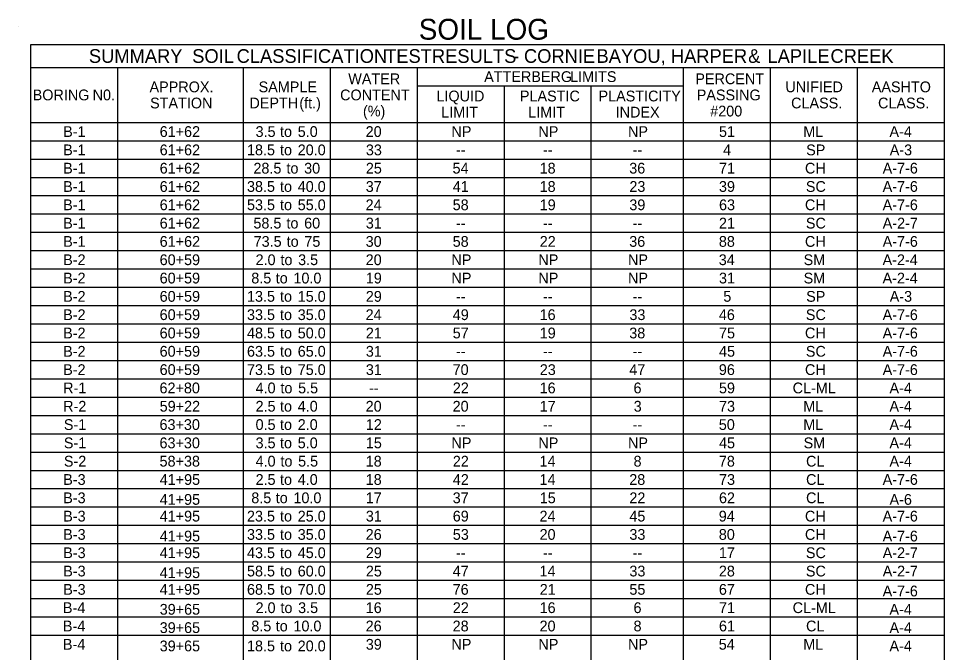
# Model space of a CAD drawing. Extents: x 977434 to 989596, y 1525697 to 1528336.
# Drawn here: x 977434 to 977967, y 1527885 to 1528249 of the extents above; entities that cross this region are included whole.
import ezdxf

# ---------------------------------------------------------------- set-up
doc = ezdxf.new("R2010")
doc.units = 0
doc.layers.add('Default', color=7, linetype='Continuous')
doc.layers.add('R_Border Prem', color=7, linetype='Continuous')

msp = doc.modelspace()

# ---------------------------------------------------------------- linework, layer by layer
at = {"layer": 'Default'}
for p, q in [((977441.26, 1528234.33), (977966.88, 1528234.33)), ((977441.26, 1528234.33), (977966.88, 1528234.33)), ((977441.26, 1527568.31), (977441.26, 1528234.33)), ((977441.26, 1527568.31), (977441.26, 1528234.33)), ((977966.88, 1527568.31), (977966.88, 1528234.33)), ((977966.88, 1527568.31), (977966.88, 1528234.33)), ((977441.26, 1528221.17), (977966.88, 1528221.17)), ((977491.28, 1527568.31), (977491.28, 1528221.17)), ((977563.67, 1527568.31), (977563.67, 1528221.17)), ((977613.69, 1527568.31), (977613.69, 1528221.17)), ((977663.71, 1527568.31), (977663.71, 1528221.17)), ((977816.83, 1527568.31), (977816.83, 1528221.17)), ((977866.85, 1527568.31), (977866.85, 1528221.17)), ((977916.87, 1527568.31), (977916.87, 1528221.17)), ((977663.71, 1528210.64), (977816.83, 1528210.64)), ((977713.72, 1527568.31), (977713.72, 1528210.64)), ((977763.74, 1527568.31), (977763.74, 1528210.64)), ((977441.26, 1528189.58), (977966.88, 1528189.58)), ((977816.83, 1528189.58), (977966.88, 1528189.58)), ((977441.26, 1528179.05), (977966.88, 1528179.05)), ((977441.26, 1528168.52), (977966.88, 1528168.52)), ((977441.26, 1528157.99), (977966.88, 1528157.99)), ((977441.26, 1528147.46), (977966.88, 1528147.46)), ((977441.26, 1528136.93), (977966.88, 1528136.93)), ((977441.26, 1528126.4), (977966.88, 1528126.4)), ((977441.26, 1528115.87), (977966.88, 1528115.87)), ((977441.26, 1528105.34), (977966.88, 1528105.34)), ((977441.26, 1528094.81), (977966.88, 1528094.81)), ((977441.26, 1528084.28), (977966.88, 1528084.28)), ((977441.26, 1528073.75), (977966.88, 1528073.75)), ((977441.26, 1528063.22), (977966.88, 1528063.22)), ((977441.26, 1528052.69), (977966.88, 1528052.69)), ((977441.26, 1528042.16), (977966.88, 1528042.16)), ((977441.26, 1528031.63), (977966.88, 1528031.63)), ((977441.26, 1528021.1), (977966.88, 1528021.1)), ((977441.26, 1528010.57), (977966.88, 1528010.57)), ((977441.26, 1528000.04), (977966.88, 1528000.04)), ((977441.26, 1527989.51), (977966.88, 1527989.51)), ((977441.26, 1527978.98), (977966.88, 1527978.98)), ((977441.26, 1527968.45), (977966.88, 1527968.45)), ((977441.26, 1527957.92), (977966.88, 1527957.92)), ((977441.26, 1527947.39), (977966.88, 1527947.39)), ((977441.26, 1527936.86), (977966.88, 1527936.86)), ((977441.26, 1527926.33), (977966.88, 1527926.33)), ((977441.26, 1527915.8), (977966.88, 1527915.8)), ((977441.26, 1527905.27), (977966.88, 1527905.27)), ((977441.26, 1527894.74), (977966.88, 1527894.74))]:
    msp.add_line(p, q, dxfattribs=at)
at = {"layer": 'R_Border Prem'}
msp.add_line((977434.24, 1528244.86), (977434.24, 1528244.86), dxfattribs=at)

# ---------------------------------------------------------------- texts
at = {"layer": 'Default'}
for s, height, p in [('SOIL LOG ', 12, (977664.46, 1528237.13)), ('SUMMARY', 7.875, (977474.72, 1528223.81)), (' SOIL', 7.875, (977531.24, 1528223.81)), (' CLASSIFICATION', 7.875, (977556.77, 1528223.81)), (' TEST', 7.875, (977642.19, 1528223.81)), (' RESULTS', 7.875, (977669.12, 1528223.81)), (' CORNIE', 7.875, (977722.06, 1528223.81)), (' BAYOU,', 7.875, (977763.79, 1528223.81)), (' HARPER', 7.875, (977806.56, 1528223.81)), (' &', 7.875, (977851.04, 1528223.81)), (' LAPILE', 7.875, (977862.14, 1528223.81)), (' CREEK', 7.875, (977898.37, 1528223.81)), (' -', 7.875, (977715.82, 1528223.81)), ('WATER', 6.188, (977623.91, 1528211.56)), ('ATTERBERG', 6.188, (977702.1, 1528212.81)), (' LIMITS', 6.188, (977749.24, 1528212.81)), ('PERCENT', 6.188, (977823.57, 1528211.56)), ('APPROX.', 6.188, (977509.6, 1528206.92)), ('SAMPLE', 6.188, (977572.34, 1528206.92)), ('UNIFIED', 6.188, (977875.36, 1528206.92)), ('AASHTO', 6.188, (977925.06, 1528206.92)), ('BORING', 6.188, (977442.39, 1528202.28)), (' N0.', 6.188, (977474.57, 1528202.28)), ('CONTENT', 6.188, (977619.23, 1528202.28)), ('LIQUID', 6.188, (977674.63, 1528201.66)), ('PLASTIC', 6.188, (977722.64, 1528201.66)), ('PLASTICITY', 6.188, (977767.87, 1528201.66)), ('PASSING', 6.188, (977824.37, 1528202.28)), ('STATION', 6.188, (977509.92, 1528197.64)), ('DEPTH', 6.188, (977567.06, 1528197.64)), (' (ft.)', 6.188, (977593.46, 1528197.64)), ('(%)', 6.188, (977632.36, 1528193)), ('#200', 6.188, (977832.13, 1528193)), ('CLASS.', 6.188, (977878.65, 1528197.64)), ('CLASS.', 6.188, (977928.67, 1528197.64)), ('LIMIT', 6.188, (977677.41, 1528192.38)), ('LIMIT', 6.188, (977727.43, 1528192.38)), ('INDEX', 6.188, (977777.73, 1528192.38)), ('B-1', 6.188, (977459.92, 1528181.22)), ('61+62', 6.188, (977515.44, 1528181.22)), ('3.5', 6.188, (977570.6, 1528181.22)), (' to', 6.188, (977582.37, 1528181.22)), (' 5.0', 6.188, (977592.55, 1528181.22)), ('20', 6.188, (977633.93, 1528181.22)), ('NP', 6.188, (977683.27, 1528181.22)), ('NP', 6.188, (977733.29, 1528181.22)), ('NP', 6.188, (977784.84, 1528181.22)), ('51', 6.188, (977837.16, 1528181.22)), ('ML', 6.188, (977885.68, 1528181.22)), ('A-4', 6.188, (977935.23, 1528181.22)), ('B-1', 6.188, (977459.92, 1528170.69)), ('61+62', 6.188, (977515.44, 1528170.69)), ('18.5', 6.188, (977565.66, 1528170.69)), (' to', 6.188, (977582.37, 1528170.69)), (' 20.0', 6.188, (977592.55, 1528170.69)), ('33', 6.188, (977634.06, 1528170.69)), ('--', 6.188, (977685.89, 1528170.69)), ('--', 6.188, (977735.91, 1528170.69)), ('--', 6.188, (977787.46, 1528170.69)), ('4', 6.19, (977839.51, 1528170.69)), ('SP', 6.188, (977887.32, 1528170.69)), ('A-3', 6.188, (977935.39, 1528170.69)), ('B-1', 6.188, (977459.92, 1528160.16)), ('61+62', 6.188, (977515.44, 1528160.16)), ('28.5', 6.188, (977569.37, 1528160.16)), (' to', 6.188, (977586.07, 1528160.16)), (' 30', 6.188, (977596.25, 1528160.16)), ('25', 6.188, (977634.04, 1528160.16)), ('54', 6.188, (977683.92, 1528160.16)), ('18', 6.188, (977733.99, 1528160.16)), ('36', 6.188, (977785.54, 1528160.16)), ('71', 6.188, (977837.16, 1528160.16)), ('CH', 6.188, (977886.63, 1528160.16)), ('A-7-6', 6.188, (977931.32, 1528160.16)), ('B-1', 6.188, (977459.92, 1528149.63)), ('61+62', 6.188, (977515.44, 1528149.63)), ('38.5', 6.188, (977565.66, 1528149.63)), (' to', 6.188, (977582.37, 1528149.63)), (' 40.0', 6.188, (977592.55, 1528149.63)), ('37', 6.188, (977633.98, 1528149.63)), ('41', 6.188, (977684.04, 1528149.63)), ('18', 6.188, (977733.99, 1528149.63)), ('23', 6.188, (977785.64, 1528149.63)), ('39', 6.188, (977837.15, 1528149.63)), ('SC', 6.188, (977887.15, 1528149.63)), ('A-7-6', 6.188, (977931.32, 1528149.63)), ('B-1', 6.188, (977459.92, 1528139.1)), ('61+62', 6.188, (977515.44, 1528139.1)), ('53.5', 6.188, (977565.66, 1528139.1)), (' to', 6.188, (977582.37, 1528139.1)), (' 55.0', 6.188, (977592.55, 1528139.1)), ('24', 6.188, (977633.9, 1528139.1)), ('58', 6.188, (977683.98, 1528139.1)), ('19', 6.188, (977734.04, 1528139.1)), ('39', 6.188, (977785.59, 1528139.1)), ('63', 6.188, (977837.2, 1528139.1)), ('CH', 6.188, (977886.63, 1528139.1)), ('A-7-6', 6.188, (977931.32, 1528139.1)), ('B-1', 6.188, (977459.92, 1528128.57)), ('61+62', 6.188, (977515.44, 1528128.57)), ('58.5', 6.188, (977569.37, 1528128.57)), (' to', 6.188, (977586.07, 1528128.57)), (' 60', 6.188, (977596.25, 1528128.57)), ('31', 6.188, (977634.02, 1528128.57)), ('--', 6.188, (977685.89, 1528128.57)), ('--', 6.188, (977735.91, 1528128.57)), ('--', 6.188, (977787.46, 1528128.57)), ('21', 6.188, (977837.16, 1528128.57)), ('SC', 6.188, (977887.15, 1528128.57)), ('A-2-7', 6.188, (977931.35, 1528128.57)), ('B-1', 6.188, (977459.92, 1528118.04)), ('61+62', 6.188, (977515.44, 1528118.04)), ('73.5', 6.188, (977569.48, 1528118.04)), (' to', 6.188, (977586.19, 1528118.04)), (' 75', 6.188, (977596.37, 1528118.04)), ('30', 6.188, (977633.93, 1528118.04)), ('58', 6.188, (977683.98, 1528118.04)), ('22', 6.188, (977734.06, 1528118.04)), ('36', 6.188, (977785.54, 1528118.04)), ('88', 6.188, (977837.1, 1528118.04)), ('CH', 6.188, (977886.63, 1528118.04)), ('A-7-6', 6.188, (977931.32, 1528118.04)), ('B-2', 6.188, (977459.92, 1528107.51)), ('60+59', 6.188, (977515.42, 1528107.51)), ('2.0', 6.188, (977570.6, 1528107.51)), (' to', 6.188, (977582.61, 1528107.51)), (' 3.5', 6.188, (977592.78, 1528107.51)), ('20', 6.188, (977633.93, 1528107.51)), ('NP', 6.188, (977683.27, 1528107.51)), ('NP', 6.188, (977733.29, 1528107.51)), ('NP', 6.188, (977784.84, 1528107.51)), ('34', 6.188, (977837.04, 1528107.51)), ('SM', 6.188, (977885.86, 1528107.51)), ('A-2-4', 6.188, (977931.27, 1528107.51)), ('B-2', 6.188, (977459.92, 1528096.98)), ('60+59', 6.188, (977515.42, 1528096.98)), ('8.5', 6.188, (977568.13, 1528096.98)), (' to', 6.188, (977579.9, 1528096.98)), (' 10.0', 6.188, (977590.08, 1528096.98)), ('19', 6.188, (977634.01, 1528096.98)), ('NP', 6.188, (977683.27, 1528096.98)), ('NP', 6.188, (977733.29, 1528096.98)), ('NP', 6.188, (977784.84, 1528096.98)), ('31', 6.188, (977837.16, 1528096.98)), ('SM', 6.188, (977885.86, 1528096.98)), ('A-2-4', 6.188, (977931.27, 1528096.98)), ('B-2', 6.188, (977459.92, 1528086.45)), ('60+59', 6.188, (977515.42, 1528086.45)), ('13.5', 6.188, (977565.66, 1528086.45)), (' to', 6.188, (977582.37, 1528086.45)), (' 15.0', 6.188, (977592.55, 1528086.45)), ('29', 6.188, (977634.01, 1528086.45)), ('--', 6.188, (977685.89, 1528086.45)), ('--', 6.188, (977735.91, 1528086.45)), ('--', 6.188, (977787.46, 1528086.45)), ('5', 6.19, (977839.65, 1528086.45)), ('SP', 6.188, (977887.32, 1528086.45)), ('A-3', 6.188, (977935.39, 1528086.45)), ('B-2', 6.188, (977459.92, 1528075.92)), ('60+59', 6.188, (977515.42, 1528075.92)), ('33.5', 6.188, (977565.66, 1528075.92)), (' 35.0', 6.188, (977592.55, 1528075.92)), ('24', 6.188, (977633.9, 1528075.92)), ('49', 6.188, (977684.02, 1528075.92)), ('16', 6.188, (977733.99, 1528075.92)), ('33', 6.188, (977785.64, 1528075.92)), ('46', 6.188, (977837.09, 1528075.92)), ('SC', 6.188, (977887.15, 1528075.92)), ('A-7-6', 6.188, (977931.32, 1528075.92)), (' to', 6.188, (977582.37, 1528075.92)), ('B-2', 6.188, (977459.92, 1528065.39)), ('60+59', 6.188, (977515.42, 1528065.39)), ('48.5', 6.188, (977565.66, 1528065.39)), (' 50.0', 6.188, (977592.55, 1528065.39)), ('21', 6.188, (977634.02, 1528065.39)), ('57', 6.188, (977684, 1528065.39)), ('19', 6.188, (977734.04, 1528065.39)), ('38', 6.188, (977785.55, 1528065.39)), ('75', 6.188, (977837.19, 1528065.39)), ('CH', 6.188, (977886.63, 1528065.39)), ('A-7-6', 6.188, (977931.32, 1528065.39)), (' to', 6.188, (977582.37, 1528065.39)), ('B-2', 6.188, (977459.92, 1528054.86)), ('60+59', 6.188, (977515.42, 1528054.86)), ('63.5', 6.188, (977565.66, 1528054.86)), (' 65.0', 6.188, (977592.55, 1528054.86)), ('31', 6.188, (977634.02, 1528054.86)), ('45', 6.188, (977837.19, 1528054.86)), ('SC', 6.188, (977887.15, 1528054.86)), ('A-7-6', 6.188, (977931.32, 1528054.86)), (' to', 6.188, (977582.37, 1528054.86)), ('--', 6.188, (977685.89, 1528054.86)), ('--', 6.188, (977735.91, 1528054.86)), ('--', 6.188, (977787.46, 1528054.86)), ('B-2', 6.188, (977459.92, 1528044.33)), ('60+59', 6.188, (977515.42, 1528044.33)), ('73.5', 6.188, (977565.66, 1528044.33)), (' to', 6.188, (977582.37, 1528044.33)), (' 75.0', 6.188, (977592.55, 1528044.33)), ('31', 6.188, (977634.02, 1528044.33)), ('70', 6.188, (977683.95, 1528044.33)), ('23', 6.188, (977734.09, 1528044.33)), ('47', 6.188, (977785.57, 1528044.33)), ('96', 6.188, (977837.09, 1528044.33)), ('CH', 6.188, (977886.63, 1528044.33)), ('A-7-6', 6.188, (977931.32, 1528044.33)), ('R-1', 6.188, (977459.92, 1528033.8)), ('62+80', 6.188, (977515.34, 1528033.8)), ('4.0', 6.188, (977570.6, 1528033.8)), (' to', 6.188, (977582.61, 1528033.8)), (' 5.5', 6.188, (977592.78, 1528033.8)), ('22', 6.188, (977684.05, 1528033.8)), ('16', 6.188, (977733.99, 1528033.8)), ('6', 6.19, (977788.01, 1528033.8)), ('59', 6.188, (977837.15, 1528033.8)), ('CL-ML', 6.188, (977879.54, 1528033.8)), ('A-4', 6.188, (977935.23, 1528033.8)), ('--', 6.188, (977635.87, 1528033.8)), ('R-2', 6.188, (977459.93, 1528023.27)), ('59+22', 6.188, (977515.44, 1528023.27)), ('2.5', 6.188, (977570.6, 1528023.27)), (' to', 6.188, (977582.37, 1528023.27)), (' 4.0', 6.188, (977592.55, 1528023.27)), ('20', 6.188, (977633.93, 1528023.27)), ('20', 6.188, (977683.95, 1528023.27)), ('17', 6.188, (977734.02, 1528023.27)), ('3', 6.19, (977788.11, 1528023.27)), ('73', 6.188, (977837.2, 1528023.27)), ('ML', 6.188, (977885.68, 1528023.27)), ('A-4', 6.188, (977935.23, 1528023.27)), ('S-1', 6.188, (977460.33, 1528012.74)), ('63+30', 6.188, (977515.34, 1528012.74)), ('0.5', 6.188, (977570.6, 1528012.74)), (' to', 6.188, (977582.37, 1528012.74)), (' 2.0', 6.188, (977592.55, 1528012.74)), ('12', 6.188, (977634.03, 1528012.74)), ('50', 6.188, (977837.07, 1528012.74)), ('ML', 6.188, (977885.68, 1528012.74)), ('A-4', 6.188, (977935.23, 1528012.74)), ('--', 6.188, (977685.89, 1528012.74)), ('--', 6.188, (977735.91, 1528012.74)), ('--', 6.188, (977787.46, 1528012.74)), ('S-1', 6.188, (977460.33, 1528002.21)), ('63+30', 6.188, (977515.34, 1528002.21)), ('3.5', 6.188, (977570.6, 1528002.21)), (' to', 6.188, (977582.37, 1528002.21)), (' 5.0', 6.188, (977592.55, 1528002.21)), ('15', 6.188, (977634.04, 1528002.21)), ('NP', 6.188, (977683.27, 1528002.21)), ('NP', 6.188, (977733.29, 1528002.21)), ('NP', 6.188, (977784.84, 1528002.21)), ('45', 6.188, (977837.19, 1528002.21)), ('SM', 6.188, (977885.86, 1528002.21)), ('A-4', 6.188, (977935.23, 1528002.21)), ('S-2', 6.188, (977460.34, 1527991.68)), ('58+38', 6.188, (977515.37, 1527991.68)), ('4.0', 6.188, (977570.6, 1527991.68)), (' to', 6.188, (977582.61, 1527991.68)), (' 5.5', 6.188, (977592.78, 1527991.68)), ('18', 6.188, (977633.96, 1527991.68)), ('22', 6.188, (977684.05, 1527991.68)), ('14', 6.188, (977733.93, 1527991.68)), ('8', 6.19, (977788.02, 1527991.68)), ('78', 6.188, (977837.1, 1527991.68)), ('CL', 6.188, (977887.25, 1527991.68)), ('A-4', 6.188, (977935.23, 1527991.68)), ('B-3', 6.188, (977459.95, 1527981.15)), ('41+95', 6.188, (977515.45, 1527981.15)), ('2.5', 6.188, (977570.6, 1527981.15)), (' to', 6.188, (977582.37, 1527981.15)), (' 4.0', 6.188, (977592.55, 1527981.15)), ('18', 6.188, (977633.96, 1527981.15)), ('42', 6.188, (977684.05, 1527981.15)), ('14', 6.188, (977733.93, 1527981.15)), ('28', 6.188, (977785.55, 1527981.15)), ('73', 6.188, (977837.2, 1527981.15)), ('CL', 6.188, (977887.25, 1527981.15)), ('A-7-6', 6.188, (977931.32, 1527981.15)), ('B-3', 6.188, (977459.95, 1527970.62)), ('41+95', 6.188, (977515.45, 1527969.69)), ('8.5', 6.188, (977568.13, 1527970.62)), (' to', 6.188, (977579.9, 1527970.62)), (' 10.0', 6.188, (977590.08, 1527970.62)), ('17', 6.188, (977633.98, 1527970.62)), ('37', 6.188, (977684, 1527970.62)), ('15', 6.188, (977734.08, 1527970.62)), ('22', 6.188, (977785.62, 1527970.62)), ('62', 6.188, (977837.17, 1527970.62)), ('CL', 6.188, (977887.25, 1527970.62)), ('A-6', 6.188, (977935.28, 1527969.69)), ('B-3', 6.188, (977459.95, 1527960.09)), ('41+95', 6.188, (977515.45, 1527960.09)), ('23.5', 6.188, (977565.66, 1527960.09)), (' to', 6.188, (977582.37, 1527960.09)), (' 25.0', 6.188, (977592.55, 1527960.09)), ('31', 6.188, (977634.02, 1527960.09)), ('69', 6.188, (977684.02, 1527960.09)), ('24', 6.188, (977733.93, 1527960.09)), ('45', 6.188, (977785.63, 1527960.09)), ('94', 6.188, (977837.04, 1527960.09)), ('CH', 6.188, (977886.63, 1527960.09)), ('A-7-6', 6.188, (977931.32, 1527960.09)), ('B-3', 6.188, (977459.95, 1527949.56)), ('41+95', 6.188, (977515.45, 1527948.63)), ('33.5', 6.188, (977565.66, 1527949.56)), (' to', 6.188, (977582.37, 1527949.56)), (' 35.0', 6.188, (977592.55, 1527949.56)), ('26', 6.188, (977633.95, 1527949.56)), ('53', 6.188, (977684.07, 1527949.56)), ('20', 6.188, (977733.96, 1527949.56)), ('33', 6.188, (977785.64, 1527949.56)), ('80', 6.188, (977837.07, 1527949.56)), ('CH', 6.188, (977886.63, 1527949.56)), ('A-7-6', 6.188, (977931.32, 1527948.63)), ('B-3', 6.188, (977459.95, 1527939.03)), ('41+95', 6.188, (977515.45, 1527939.03)), ('43.5', 6.188, (977565.66, 1527939.03)), (' to', 6.188, (977582.37, 1527939.03)), (' 45.0', 6.188, (977592.55, 1527939.03)), ('29', 6.188, (977634.01, 1527939.03)), ('17', 6.188, (977837.12, 1527939.03)), ('SC', 6.188, (977887.15, 1527939.03)), ('A-2-7', 6.188, (977931.35, 1527939.03)), ('--', 6.188, (977685.89, 1527939.03)), ('--', 6.188, (977735.91, 1527939.03)), ('--', 6.188, (977787.46, 1527939.03)), ('B-3', 6.188, (977459.95, 1527928.5)), ('41+95', 6.188, (977515.45, 1527927.57)), ('58.5', 6.188, (977565.66, 1527928.5)), (' to', 6.188, (977582.37, 1527928.5)), (' 60.0', 6.188, (977592.55, 1527928.5)), ('25', 6.188, (977634.04, 1527928.5)), ('47', 6.188, (977684, 1527928.5)), ('14', 6.188, (977733.93, 1527928.5)), ('33', 6.188, (977785.64, 1527928.5)), ('28', 6.188, (977837.1, 1527928.5)), ('SC', 6.188, (977887.15, 1527928.5)), ('A-2-7', 6.188, (977931.35, 1527928.5)), ('B-3', 6.188, (977459.95, 1527917.97)), ('41+95', 6.188, (977515.45, 1527917.97)), ('68.5', 6.188, (977565.66, 1527917.97)), (' to', 6.188, (977582.37, 1527917.97)), (' 70.0', 6.188, (977592.55, 1527917.97)), ('25', 6.188, (977634.04, 1527917.97)), ('76', 6.188, (977683.97, 1527917.97)), ('21', 6.188, (977734.06, 1527917.97)), ('55', 6.188, (977785.63, 1527917.97)), ('67', 6.188, (977837.12, 1527917.97)), ('CH', 6.188, (977886.63, 1527917.97)), ('A-7-6', 6.188, (977931.32, 1527917.04)), ('B-4', 6.188, (977459.79, 1527907.44)), ('39+65', 6.188, (977515.45, 1527906.51)), ('2.0', 6.188, (977570.6, 1527907.44)), (' to', 6.188, (977582.61, 1527907.44)), (' 3.5', 6.188, (977592.78, 1527907.44)), ('16', 6.188, (977633.95, 1527907.44)), ('22', 6.188, (977684.05, 1527907.44)), ('16', 6.188, (977733.99, 1527907.44)), ('6', 6.19, (977788.01, 1527907.44)), ('71', 6.188, (977837.16, 1527907.44)), ('CL-ML', 6.188, (977879.54, 1527907.44)), ('A-4', 6.188, (977935.23, 1527906.51)), ('B-4', 6.188, (977459.79, 1527896.91)), ('39+65', 6.188, (977515.45, 1527895.98)), ('8.5', 6.188, (977568.13, 1527896.91)), (' to', 6.188, (977579.9, 1527896.91)), (' 10.0', 6.188, (977590.08, 1527896.91)), ('26', 6.188, (977633.95, 1527896.91)), ('28', 6.188, (977683.98, 1527896.91)), ('20', 6.188, (977733.96, 1527896.91)), ('8', 6.19, (977788.02, 1527896.91)), ('61', 6.188, (977837.16, 1527896.91)), ('CL', 6.188, (977887.25, 1527896.91)), ('A-4', 6.188, (977935.23, 1527895.98)), ('B-4', 6.188, (977459.79, 1527886.38)), ('39+65', 6.188, (977515.45, 1527885.45)), ('18.5', 6.188, (977565.66, 1527885.45)), (' to', 6.188, (977582.37, 1527885.45)), (' 20.0', 6.188, (977592.55, 1527885.45)), ('39', 6.188, (977634.01, 1527886.38)), ('NP', 6.188, (977683.27, 1527886.38)), ('NP', 6.188, (977733.29, 1527886.38)), ('NP', 6.188, (977784.84, 1527886.38)), ('54', 6.188, (977837.04, 1527886.38)), ('ML', 6.188, (977885.68, 1527886.38)), ('A-4', 6.188, (977935.23, 1527885.45))]:
    msp.add_text(s, height=height, dxfattribs=at).set_placement(p)

doc.saveas('drawing.dxf')
